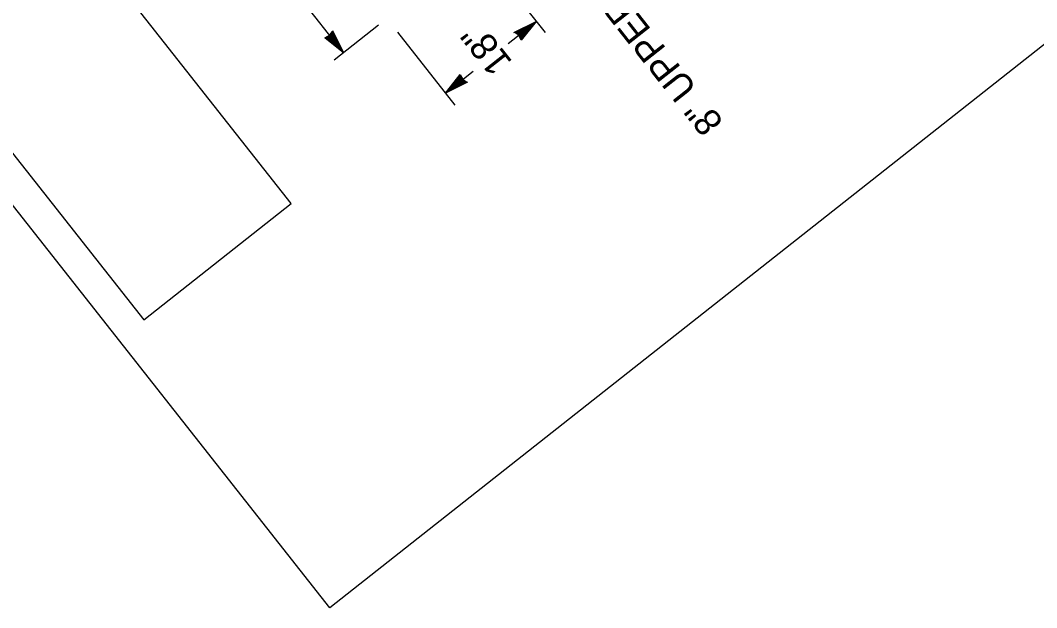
# Model space of a CAD drawing. Extents: x 672126 to 673696, y 1673540 to 1674900.
# Drawn here: x 672217.5 to 672375.7, y 1674518.5 to 1674609.9 of the extents above; entities that cross this region are included whole.
import ezdxf

# ---------------------------------------------------------------- set-up
doc = ezdxf.new("R2010")
doc.units = 0
doc.layers.add('61', color=7, linetype='Continuous')
doc.layers.add('Level 1', color=7, linetype='Continuous')

msp = doc.modelspace()

# ---------------------------------------------------------------- linework, layer by layer
at = {"layer": '61'}
msp.add_lwpolyline([(672259.69, 1674581.41), (672186.16, 1674674.68), (672163.21, 1674656.58), (672236.74, 1674563.31)], close=True, dxfattribs=at)
at = {"layer": 'Level 1'}
for p, q in [((672525.22, 1674723.12), (672265.69, 1674518.51)), ((672265.69, 1674518.51), (672125.9, 1674695.83)), ((672267.81, 1674604.9), (672253.19, 1674623.43)), ((672290.35, 1674619.22), (672299.18, 1674608.02)), ((672273.27, 1674609.2), (672266.36, 1674603.76)), ((672293.47, 1674606.33), (672297.81, 1674609.75)), ((672294.35, 1674608.05), (672297.81, 1674609.75)), ((672294.54, 1674608.1), (672297.39, 1674609.39)), ((672294.7, 1674608.06), (672297.55, 1674609.49)), ((672294.82, 1674607.99), (672297.02, 1674609.14)), ((672294.82, 1674607.99), (672296.95, 1674609.02)), ((672295, 1674607.93), (672296.51, 1674608.68)), ((672297.02, 1674609.14), (672295.46, 1674607.43)), ((672297.81, 1674609.75), (672295.49, 1674606.84)), ((672297.59, 1674609.52), (672295.5, 1674606.99)), ((672297.24, 1674609.24), (672295.51, 1674607.16)), ((672296.95, 1674609.02), (672295.51, 1674607.29)), ((672296.51, 1674608.68), (672295.52, 1674607.57)), ((672296.58, 1674608.76), (672296.15, 1674608.56)), ((672296.22, 1674608.42), (672296.58, 1674608.76)), ((672297.34, 1674609.46), (672296.54, 1674609.03)), ((672296.54, 1674609.03), (672297.24, 1674609.24)), ((672297.55, 1674609.49), (672297.34, 1674609.46)), ((672297.39, 1674609.39), (672297.59, 1674609.52)), ((672264.9, 1674607.22), (672265.66, 1674607.61)), ((672267.81, 1674604.9), (672264.9, 1674607.22)), ((672265.05, 1674607.2), (672265.61, 1674607.54)), ((672267.57, 1674605.11), (672265.05, 1674607.2)), ((672265.22, 1674607.2), (672265.48, 1674607.33)), ((672267.3, 1674605.46), (672265.22, 1674607.2)), ((672265.35, 1674607.2), (672266.05, 1674607.88)), ((672267.07, 1674605.76), (672265.35, 1674607.2)), ((672265.48, 1674607.33), (672266.05, 1674607.88)), ((672265.48, 1674607.24), (672265.99, 1674607.7)), ((672267.2, 1674605.68), (672265.48, 1674607.24)), ((672265.61, 1674607.54), (672266.09, 1674608.21)), ((672265.88, 1674607.62), (672265.61, 1674607.24)), ((672265.61, 1674607.24), (672266.37, 1674606.74)), ((672265.63, 1674607.18), (672265.95, 1674607.54)), ((672266.73, 1674606.19), (672265.63, 1674607.18)), ((672265.66, 1674607.61), (672265.97, 1674607.85)), ((672265.75, 1674607.15), (672265.9, 1674607.43)), ((672266.46, 1674606.58), (672265.75, 1674607.15)), ((672265.83, 1674607.18), (672265.89, 1674607.26)), ((672266.17, 1674606.91), (672265.83, 1674607.18)), ((672265.89, 1674607.26), (672265.88, 1674607.62)), ((672265.9, 1674607.43), (672266.17, 1674606.91)), ((672265.95, 1674607.54), (672266.46, 1674606.58)), ((672265.97, 1674607.85), (672266.16, 1674608.16)), ((672265.99, 1674607.7), (672266.73, 1674606.19)), ((672266.09, 1674608.21), (672266.02, 1674607.99)), ((672266.02, 1674607.99), (672266.12, 1674608)), ((672266.05, 1674607.88), (672267.07, 1674605.76)), ((672266.05, 1674607.88), (672267.2, 1674605.68)), ((672266.1, 1674608.36), (672267.81, 1674604.9)), ((672266.12, 1674608), (672267.54, 1674605.16)), ((672266.16, 1674608.16), (672267.45, 1674605.32)), ((672276.21, 1674608.07), (672285.17, 1674596.71)), ((672295.16, 1674607.56), (672294.49, 1674608.03)), ((672294.49, 1674608.03), (672294.71, 1674607.97)), ((672294.85, 1674607.91), (672294.54, 1674608.1)), ((672294.71, 1674607.97), (672294.7, 1674608.06)), ((672295.37, 1674607.42), (672294.82, 1674607.99)), ((672295.51, 1674607.29), (672294.82, 1674607.99)), ((672295.09, 1674607.6), (672294.85, 1674607.91)), ((672295.46, 1674607.43), (672295, 1674607.93)), ((672295.44, 1674607.84), (672295.09, 1674607.83)), ((672295.09, 1674607.83), (672295.46, 1674607.56)), ((672295.49, 1674606.84), (672295.09, 1674607.6)), ((672295.5, 1674606.99), (672295.16, 1674607.56)), ((672295.17, 1674607.89), (672296.13, 1674608.41)), ((672295.52, 1674607.57), (672295.17, 1674607.89)), ((672295.27, 1674607.84), (672295.79, 1674608.11)), ((672295.55, 1674607.7), (672295.27, 1674607.84)), ((672295.51, 1674607.16), (672295.37, 1674607.42)), ((672295.52, 1674607.78), (672295.44, 1674607.84)), ((672295.46, 1674607.56), (672295.97, 1674608.32)), ((672295.79, 1674608.11), (672295.52, 1674607.78)), ((672296.13, 1674608.41), (672295.55, 1674607.7)), ((672295.97, 1674608.32), (672296.22, 1674608.42)), ((672266.37, 1674606.74), (672266.47, 1674606.48)), ((672266.47, 1674606.48), (672266.82, 1674606.12)), ((672266.82, 1674606.12), (672266.61, 1674606.56)), ((672267.51, 1674605.36), (672267.09, 1674606.16)), ((672267.09, 1674606.16), (672267.3, 1674605.46)), ((672267.45, 1674605.32), (672267.57, 1674605.11)), ((672267.54, 1674605.16), (672267.51, 1674605.36)), ((672283.67, 1674598.61), (672288, 1674602.02)), ((672283.67, 1674598.61), (672285.99, 1674601.52)), ((672283.89, 1674598.85), (672285.97, 1674601.37)), ((672284.24, 1674599.12), (672285.97, 1674601.2)), ((672284.46, 1674599.22), (672286.02, 1674600.94)), ((672284.53, 1674599.34), (672285.97, 1674601.07)), ((672284.97, 1674599.68), (672285.96, 1674600.79)), ((672285.35, 1674599.95), (672285.92, 1674600.66)), ((672286.02, 1674600.8), (672285.51, 1674600.05)), ((672285.92, 1674600.66), (672286.21, 1674600.52)), ((672285.96, 1674600.79), (672286.31, 1674600.47)), ((672285.97, 1674601.37), (672286.32, 1674600.8)), ((672285.97, 1674601.2), (672286.11, 1674600.94)), ((672285.97, 1674601.07), (672286.65, 1674600.37)), ((672285.99, 1674601.52), (672286.39, 1674600.76)), ((672286.02, 1674600.94), (672286.48, 1674600.43)), ((672286.39, 1674600.53), (672286.02, 1674600.8)), ((672286.11, 1674600.94), (672286.65, 1674600.37)), ((672286.32, 1674600.8), (672286.99, 1674600.33)), ((672286.39, 1674600.76), (672286.63, 1674600.45)), ((672287.13, 1674600.31), (672283.67, 1674598.61)), ((672286.78, 1674600.3), (672283.93, 1674598.88)), ((672286.94, 1674600.26), (672284.09, 1674598.97)), ((672284.14, 1674598.91), (672284.94, 1674599.33)), ((672284.94, 1674599.33), (672284.24, 1674599.12)), ((672286.65, 1674600.37), (672284.46, 1674599.22)), ((672286.65, 1674600.37), (672284.53, 1674599.34)), ((672285.26, 1674599.95), (672284.9, 1674599.6)), ((672284.9, 1674599.6), (672285.33, 1674599.81)), ((672286.48, 1674600.43), (672284.97, 1674599.68)), ((672285.51, 1674600.05), (672285.26, 1674599.95)), ((672286.31, 1674600.47), (672285.35, 1674599.95)), ((672285.69, 1674600.25), (672285.95, 1674600.59)), ((672286.21, 1674600.52), (672285.69, 1674600.25)), ((672285.95, 1674600.59), (672286.04, 1674600.52)), ((672286.04, 1674600.52), (672286.39, 1674600.53)), ((672286.63, 1674600.45), (672286.94, 1674600.26)), ((672286.99, 1674600.33), (672286.77, 1674600.39)), ((672286.77, 1674600.39), (672286.78, 1674600.3)), ((672284.09, 1674598.97), (672283.89, 1674598.85)), ((672283.93, 1674598.88), (672284.14, 1674598.91))]:
    msp.add_line(p, q, dxfattribs=at)

# ---------------------------------------------------------------- texts
for s, p in [('8" UPPERCASE', (672327.11, 1674594.13)), ('18"', (672294.22, 1674603.45))]:
    msp.add_text(s, height=4.2, rotation=128.2505, dxfattribs=at).set_placement(p)

doc.saveas('drawing.dxf')
